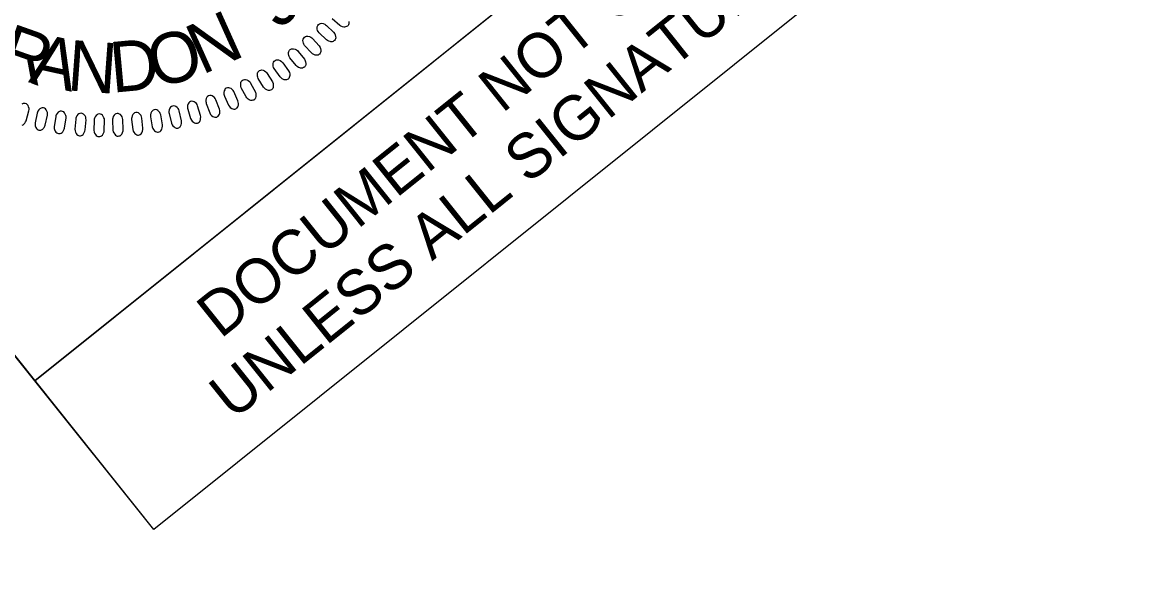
# Model space of a CAD drawing. Extents: x 473546 to 475544, y 505920 to 507827.
# Drawn here: x 474796.9 to 474934.4, y 507532.4 to 507600.7 of the extents above; entities that cross this region are included whole.
import ezdxf

# ---------------------------------------------------------------- set-up
doc = ezdxf.new("R2010")
doc.units = 0
for name, color, linetype in [('Sheet Clip Boundary CELL', 7, 'Continuous'), ('Sheet Plan CELL', 7, 'Continuous'), ('Sheet Profile Grid Minor CELL', 7, 'Continuous'), ('Sheet Sticker Exception Certification CELL', 7, 'Continuous')]:
    doc.layers.add(name, color=color, linetype=linetype)

msp = doc.modelspace()

# ---------------------------------------------------------------- linework, layer by layer
at = {"layer": 'Sheet Clip Boundary CELL'}
msp.add_lwpolyline([(474813.14, 507538.12), (474704.64, 507673.67), (473746.99, 506907.14), (474401.7, 506086.25), (475384.17, 506871.79), (475333.84, 506934.75), (475466.73, 507041), (474969.31, 507663.12)], close=True, dxfattribs=at)
at = {"layer": 'Sheet Plan CELL'}
msp.add_lwpolyline([(474728.16, 507644.28), (474806.27, 507706.8), (474876.57, 507618.96), (474798.45, 507556.47)], close=True, dxfattribs=at)
at = {"layer": 'Sheet Profile Grid Minor CELL'}
for points in [[(474834.46, 507600.3), (474835.34, 507599.45), (474835.47, 507599.27), (474835.53, 507599.14), (474835.57, 507598.94), (474835.59, 507598.79), (474835.56, 507598.65), (474835.52, 507598.55), (474835.46, 507598.46), (474835.36, 507598.39), (474835.26, 507598.33), (474835.14, 507598.29), (474835, 507598.29), (474834.9, 507598.3), (474834.75, 507598.36), (474834.58, 507598.44), (474834.45, 507598.53), (474833.54, 507599.4), (474833.43, 507599.54), (474833.36, 507599.67), (474833.31, 507599.84), (474833.29, 507600.02), (474833.3, 507600.14), (474833.37, 507600.3), (474833.46, 507600.42), (474833.59, 507600.5), (474833.7, 507600.54), (474833.86, 507600.56), (474834.06, 507600.53), (474834.24, 507600.45), (474834.35, 507600.38)], [(474832.73, 507598.67), (474833.55, 507597.77), (474833.67, 507597.58), (474833.73, 507597.44), (474833.76, 507597.24), (474833.76, 507597.09), (474833.73, 507596.96), (474833.68, 507596.86), (474833.61, 507596.77), (474833.52, 507596.71), (474833.41, 507596.65), (474833.29, 507596.62), (474833.15, 507596.63), (474833.05, 507596.65), (474832.9, 507596.71), (474832.73, 507596.8), (474832.61, 507596.91), (474831.76, 507597.83), (474831.66, 507597.97), (474831.6, 507598.11), (474831.56, 507598.29), (474831.55, 507598.46), (474831.57, 507598.59), (474831.64, 507598.74), (474831.74, 507598.85), (474831.88, 507598.92), (474831.99, 507598.96), (474832.15, 507598.97), (474832.35, 507598.92), (474832.52, 507598.84), (474832.63, 507598.76)], [(474830.96, 507597.1), (474831.72, 507596.14), (474831.83, 507595.95), (474831.88, 507595.81), (474831.9, 507595.6), (474831.89, 507595.46), (474831.85, 507595.32), (474831.8, 507595.23), (474831.72, 507595.14), (474831.62, 507595.09), (474831.51, 507595.04), (474831.39, 507595.02), (474831.24, 507595.03), (474831.15, 507595.06), (474831, 507595.13), (474830.84, 507595.23), (474830.73, 507595.34), (474829.94, 507596.32), (474829.85, 507596.47), (474829.8, 507596.6), (474829.76, 507596.78), (474829.77, 507596.96), (474829.79, 507597.09), (474829.88, 507597.23), (474829.98, 507597.34), (474830.12, 507597.4), (474830.24, 507597.43), (474830.4, 507597.43), (474830.6, 507597.37), (474830.76, 507597.27), (474830.87, 507597.19)], [(474829.08, 507595.69), (474829.78, 507594.68), (474829.88, 507594.48), (474829.91, 507594.34), (474829.92, 507594.13), (474829.9, 507593.99), (474829.86, 507593.86), (474829.79, 507593.76), (474829.71, 507593.68), (474829.61, 507593.64), (474829.5, 507593.59), (474829.38, 507593.58), (474829.23, 507593.6), (474829.14, 507593.63), (474829, 507593.72), (474828.84, 507593.83), (474828.73, 507593.95), (474828.01, 507594.97), (474827.93, 507595.12), (474827.88, 507595.26), (474827.87, 507595.45), (474827.88, 507595.62), (474827.91, 507595.75), (474828, 507595.88), (474828.12, 507595.99), (474828.26, 507596.04), (474828.38, 507596.06), (474828.54, 507596.05), (474828.73, 507595.98), (474828.89, 507595.87), (474828.99, 507595.78)], [(474825.09, 507593.17), (474825.67, 507592.08), (474825.73, 507591.87), (474825.75, 507591.72), (474825.73, 507591.52), (474825.7, 507591.38), (474825.64, 507591.26), (474825.56, 507591.17), (474825.47, 507591.1), (474825.37, 507591.07), (474825.25, 507591.04), (474825.13, 507591.04), (474824.99, 507591.08), (474824.9, 507591.12), (474824.77, 507591.22), (474824.63, 507591.36), (474824.54, 507591.49), (474823.94, 507592.59), (474823.88, 507592.75), (474823.86, 507592.9), (474823.86, 507593.08), (474823.9, 507593.26), (474823.94, 507593.37), (474824.05, 507593.5), (474824.18, 507593.59), (474824.33, 507593.62), (474824.44, 507593.63), (474824.6, 507593.6), (474824.79, 507593.5), (474824.93, 507593.38), (474825.02, 507593.28)], [(474827.14, 507594.39), (474827.78, 507593.35), (474827.87, 507593.14), (474827.89, 507592.99), (474827.89, 507592.79), (474827.86, 507592.64), (474827.81, 507592.52), (474827.74, 507592.43), (474827.65, 507592.35), (474827.55, 507592.31), (474827.43, 507592.28), (474827.31, 507592.27), (474827.17, 507592.3), (474827.08, 507592.34), (474826.94, 507592.43), (474826.8, 507592.55), (474826.69, 507592.68), (474826.03, 507593.75), (474825.96, 507593.9), (474825.93, 507594.05), (474825.92, 507594.23), (474825.94, 507594.41), (474825.98, 507594.52), (474826.09, 507594.66), (474826.2, 507594.75), (474826.35, 507594.8), (474826.47, 507594.81), (474826.63, 507594.79), (474826.82, 507594.71), (474826.97, 507594.59), (474827.06, 507594.49)], [(474821.85, 507591.58), (474822.35, 507590.46), (474822.48, 507590.28), (474822.58, 507590.17), (474822.76, 507590.06), (474822.89, 507590), (474823.02, 507589.98), (474823.14, 507589.98), (474823.25, 507590.01), (474823.34, 507590.08), (474823.44, 507590.15), (474823.51, 507590.25), (474823.56, 507590.38), (474823.58, 507590.48), (474823.58, 507590.65), (474823.56, 507590.83), (474823.52, 507590.99), (474823.01, 507592.14), (474822.92, 507592.28), (474822.82, 507592.39), (474822.67, 507592.5), (474822.51, 507592.58), (474822.39, 507592.61), (474822.23, 507592.6), (474822.08, 507592.56), (474821.96, 507592.46), (474821.89, 507592.37), (474821.81, 507592.23), (474821.77, 507592.03), (474821.78, 507591.84), (474821.81, 507591.71)], [(474817.32, 507589.97), (474817.68, 507588.8), (474817.78, 507588.6), (474817.87, 507588.48), (474818.03, 507588.36), (474818.15, 507588.28), (474818.28, 507588.24), (474818.4, 507588.23), (474818.51, 507588.24), (474818.61, 507588.29), (474818.72, 507588.36), (474818.8, 507588.44), (474818.87, 507588.57), (474818.9, 507588.67), (474818.92, 507588.83), (474818.93, 507589.02), (474818.9, 507589.18), (474818.54, 507590.38), (474818.47, 507590.54), (474818.39, 507590.66), (474818.25, 507590.78), (474818.11, 507590.88), (474817.99, 507590.93), (474817.82, 507590.94), (474817.67, 507590.92), (474817.54, 507590.83), (474817.46, 507590.76), (474817.36, 507590.62), (474817.3, 507590.43), (474817.29, 507590.23), (474817.3, 507590.1)], [(474819.61, 507590.65), (474820.04, 507589.5), (474820.15, 507589.31), (474820.25, 507589.2), (474820.42, 507589.08), (474820.55, 507589.01), (474820.68, 507588.98), (474820.79, 507588.97), (474820.9, 507589), (474821, 507589.05), (474821.1, 507589.12), (474821.18, 507589.22), (474821.24, 507589.35), (474821.27, 507589.44), (474821.28, 507589.61), (474821.27, 507589.8), (474821.24, 507589.95), (474820.8, 507591.13), (474820.72, 507591.28), (474820.63, 507591.4), (474820.49, 507591.51), (474820.33, 507591.61), (474820.22, 507591.65), (474820.05, 507591.65), (474819.9, 507591.61), (474819.77, 507591.52), (474819.69, 507591.44), (474819.61, 507591.3), (474819.56, 507591.1), (474819.56, 507590.91), (474819.58, 507590.78)], [(474798.73, 507589.47), (474798.48, 507588.27), (474798.48, 507588.05), (474798.5, 507587.9), (474798.57, 507587.71), (474798.65, 507587.59), (474798.74, 507587.49), (474798.84, 507587.43), (474798.94, 507587.38), (474799.05, 507587.38), (474799.18, 507587.39), (474799.29, 507587.42), (474799.42, 507587.5), (474799.49, 507587.57), (474799.59, 507587.7), (474799.68, 507587.86), (474799.74, 507588.01), (474800, 507589.24), (474800.01, 507589.41), (474800, 507589.56), (474799.94, 507589.73), (474799.86, 507589.89), (474799.78, 507589.99), (474799.64, 507590.08), (474799.5, 507590.13), (474799.34, 507590.12), (474799.23, 507590.09), (474799.08, 507590.02), (474798.93, 507589.88), (474798.83, 507589.72), (474798.78, 507589.6)], [(474801.02, 507589.04), (474800.85, 507587.82), (474800.85, 507587.6), (474800.88, 507587.45), (474800.97, 507587.27), (474801.05, 507587.15), (474801.15, 507587.05), (474801.25, 507587), (474801.36, 507586.96), (474801.47, 507586.97), (474801.59, 507586.98), (474801.71, 507587.02), (474801.82, 507587.11), (474801.89, 507587.18), (474801.98, 507587.32), (474802.07, 507587.49), (474802.11, 507587.64), (474802.3, 507588.88), (474802.3, 507589.05), (474802.27, 507589.2), (474802.21, 507589.37), (474802.12, 507589.52), (474802.03, 507589.62), (474801.88, 507589.7), (474801.74, 507589.74), (474801.59, 507589.72), (474801.48, 507589.69), (474801.34, 507589.61), (474801.19, 507589.45), (474801.1, 507589.29), (474801.05, 507589.16)], [(474803.49, 507588.73), (474803.39, 507587.51), (474803.41, 507587.29), (474803.45, 507587.14), (474803.55, 507586.97), (474803.64, 507586.85), (474803.74, 507586.76), (474803.84, 507586.71), (474803.95, 507586.68), (474804.07, 507586.69), (474804.19, 507586.72), (474804.3, 507586.77), (474804.41, 507586.86), (474804.47, 507586.93), (474804.55, 507587.08), (474804.63, 507587.25), (474804.66, 507587.41), (474804.77, 507588.66), (474804.76, 507588.83), (474804.73, 507588.97), (474804.65, 507589.14), (474804.55, 507589.29), (474804.46, 507589.37), (474804.31, 507589.45), (474804.16, 507589.48), (474804.01, 507589.45), (474803.9, 507589.41), (474803.76, 507589.32), (474803.63, 507589.16), (474803.55, 507588.99), (474803.51, 507588.86)], [(474805.76, 507588.59), (474805.74, 507587.37), (474805.78, 507587.15), (474805.82, 507587.01), (474805.93, 507586.83), (474806.03, 507586.72), (474806.14, 507586.64), (474806.24, 507586.6), (474806.36, 507586.58), (474806.47, 507586.6), (474806.59, 507586.62), (474806.69, 507586.68), (474806.8, 507586.78), (474806.86, 507586.86), (474806.93, 507587.01), (474806.99, 507587.19), (474807.02, 507587.35), (474807.05, 507588.6), (474807.03, 507588.77), (474806.98, 507588.91), (474806.9, 507589.07), (474806.79, 507589.21), (474806.69, 507589.3), (474806.54, 507589.36), (474806.39, 507589.38), (474806.24, 507589.34), (474806.13, 507589.29), (474806, 507589.2), (474805.88, 507589.03), (474805.81, 507588.85), (474805.78, 507588.72)], [(474808.03, 507588.61), (474808.08, 507587.39), (474808.13, 507587.17), (474808.19, 507587.03), (474808.31, 507586.87), (474808.41, 507586.76), (474808.53, 507586.69), (474808.63, 507586.65), (474808.75, 507586.64), (474808.86, 507586.66), (474808.98, 507586.7), (474809.08, 507586.76), (474809.18, 507586.87), (474809.23, 507586.95), (474809.29, 507587.1), (474809.35, 507587.29), (474809.36, 507587.45), (474809.31, 507588.7), (474809.28, 507588.87), (474809.23, 507589.01), (474809.13, 507589.16), (474809.01, 507589.3), (474808.91, 507589.37), (474808.75, 507589.43), (474808.6, 507589.44), (474808.45, 507589.39), (474808.35, 507589.34), (474808.23, 507589.23), (474808.12, 507589.06), (474808.06, 507588.87), (474808.04, 507588.74)], [(474810.39, 507588.7), (474810.53, 507587.48), (474810.59, 507587.26), (474810.66, 507587.13), (474810.79, 507586.97), (474810.9, 507586.88), (474811.02, 507586.81), (474811.12, 507586.78), (474811.24, 507586.77), (474811.35, 507586.8), (474811.46, 507586.85), (474811.56, 507586.92), (474811.65, 507587.03), (474811.7, 507587.12), (474811.75, 507587.27), (474811.79, 507587.46), (474811.8, 507587.62), (474811.67, 507588.87), (474811.63, 507589.03), (474811.57, 507589.17), (474811.46, 507589.32), (474811.34, 507589.44), (474811.23, 507589.51), (474811.07, 507589.55), (474810.92, 507589.56), (474810.77, 507589.5), (474810.67, 507589.44), (474810.56, 507589.33), (474810.46, 507589.15), (474810.41, 507588.96), (474810.4, 507588.83)], [(474812.73, 507589.01), (474812.94, 507587.8), (474813.01, 507587.59), (474813.09, 507587.46), (474813.23, 507587.31), (474813.34, 507587.22), (474813.47, 507587.16), (474813.58, 507587.14), (474813.69, 507587.14), (474813.8, 507587.18), (474813.91, 507587.23), (474814, 507587.31), (474814.09, 507587.42), (474814.14, 507587.51), (474814.18, 507587.67), (474814.2, 507587.86), (474814.2, 507588.02), (474813.99, 507589.26), (474813.94, 507589.42), (474813.87, 507589.55), (474813.76, 507589.69), (474813.62, 507589.81), (474813.51, 507589.87), (474813.35, 507589.91), (474813.2, 507589.9), (474813.06, 507589.84), (474812.96, 507589.77), (474812.85, 507589.65), (474812.77, 507589.46), (474812.73, 507589.27), (474812.72, 507589.14)], [(474815.03, 507589.43), (474815.31, 507588.24), (474815.4, 507588.03), (474815.49, 507587.91), (474815.63, 507587.77), (474815.75, 507587.69), (474815.88, 507587.64), (474815.99, 507587.62), (474816.11, 507587.63), (474816.21, 507587.67), (474816.32, 507587.73), (474816.41, 507587.81), (474816.49, 507587.94), (474816.53, 507588.03), (474816.56, 507588.19), (474816.57, 507588.38), (474816.56, 507588.54), (474816.27, 507589.76), (474816.21, 507589.92), (474816.13, 507590.05), (474816.01, 507590.18), (474815.87, 507590.29), (474815.76, 507590.34), (474815.59, 507590.37), (474815.44, 507590.35), (474815.3, 507590.28), (474815.21, 507590.2), (474815.11, 507590.08), (474815.04, 507589.89), (474815.01, 507589.69), (474815.01, 507589.56)]]:
    msp.add_lwpolyline(points, close=True, dxfattribs=at)
for points in [[(474837.21, 507600.78), (474837.23, 507600.63), (474837.22, 507600.49), (474837.18, 507600.39), (474837.12, 507600.29), (474837.03, 507600.22), (474836.93, 507600.15), (474836.82, 507600.11), (474836.68, 507600.09), (474836.58, 507600.1), (474836.42, 507600.14), (474836.24, 507600.22), (474836.11, 507600.3), (474835.15, 507601.11)], [(474796.89, 507587.98), (474797.02, 507588.05), (474797.1, 507588.11), (474797.2, 507588.24), (474797.31, 507588.4), (474797.37, 507588.54), (474797.71, 507589.75), (474797.73, 507589.92), (474797.73, 507590.07), (474797.68, 507590.25), (474797.61, 507590.41), (474797.54, 507590.52), (474797.4, 507590.61), (474797.27, 507590.67), (474797.11, 507590.67), (474797, 507590.65), (474796.85, 507590.59)]]:
    msp.add_lwpolyline(points, dxfattribs=at)
at = {"layer": 'Sheet Sticker Exception Certification CELL'}
for p, q in [((474798.45, 507556.47), (474954.63, 507681.46)), ((474798.45, 507556.47), (474954.63, 507681.46)), ((474969.32, 507663.11), (474813.14, 507538.12)), ((474969.32, 507663.11), (474813.14, 507538.12)), ((474813.14, 507538.12), (474798.45, 507556.47)), ((474813.14, 507538.12), (474798.45, 507556.47))]:
    msp.add_line(p, q, dxfattribs=at)

# ---------------------------------------------------------------- texts
at = {"layer": 'Sheet Profile Grid Minor CELL'}
for s, rotation, p in [('J', 42.8169, (474828.69, 507599.69)), ('N', 24.2217, (474819.08, 507594.16)), ('R', 340.536, (474793.57, 507594.72)), ('O', 14.1219, (474813.27, 507592.55)), ('A', 347.6528, (474797.58, 507593.3)), ('N', 355.764, (474802.33, 507592.3)), ('D', 5.2537, (474808, 507591.99))]:
    msp.add_text(s, height=6.24, rotation=rotation, dxfattribs=at).set_placement(p)
at = {"layer": 'Sheet Sticker Exception Certification CELL'}
for s, p in [('DOCUMENT NOT CONSIDERED FINAL', (474821.37, 507561.56)), ('DOCUMENT NOT CONSIDERED FINAL', (474821.37, 507561.56)), ('UNLESS ALL SIGNATURES COMPLETED', (474822.91, 507551.52)), ('UNLESS ALL SIGNATURES COMPLETED', (474822.91, 507551.52))]:
    msp.add_text(s, height=5.5, rotation=38.6712, dxfattribs=at).set_placement(p)

doc.saveas('drawing.dxf')
